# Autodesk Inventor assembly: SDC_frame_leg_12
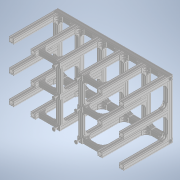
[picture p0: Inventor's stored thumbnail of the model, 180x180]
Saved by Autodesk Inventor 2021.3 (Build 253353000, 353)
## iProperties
Created: 2022-02
Part Number: SDC_frame_leg_12
Description: CAx-IF Rec.Pracs.---Model Styling and Organization---1.2---2011-12-15
Document SubType Name: Assembly
Designer: kengo
Title: SDC_frame_leg_12.stp
Sending System: 3D_Kernel_IO2017 Sp2 by CT CoreTechnologie
Preprocessor: STEP Interface 2017 Sp2 by CT CoreTechnologie
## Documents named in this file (102)
- C:\Users\kengo\Documents\S2S_frame\SDC345\frame_misumi_ver12\SDC_frame_leg_12.iam
- C:\Users\kengo\Documents\S2S_frame\SDC345\frame_misumi_ver12\HBLFSDW8-90-SET(1).iam
- C:\Users\kengo\Documents\S2S_frame\SDC345\frame_misumi_ver12\HBLFSDW8-90-SET(2).iam
- C:\Users\kengo\Documents\S2S_frame\SDC345\frame_misumi_ver12\HBLFSDW8-90-SET(3).iam
- C:\Users\kengo\Documents\S2S_frame\SDC345\frame_misumi_ver12\HBLFSDW8-90-SET(4).iam
- C:\Users\kengo\Documents\S2S_frame\SDC345\frame_misumi_ver12\HBLFSDW8-90-SET(5).iam
- C:\Users\kengo\Documents\S2S_frame\SDC345\frame_misumi_ver12\HBLFSDW8-90-SET(6).iam
- C:\Users\kengo\Documents\S2S_frame\SDC345\frame_misumi_ver12\HBLFSDW8-90-SET(7).iam
- C:\Users\kengo\Documents\S2S_frame\SDC345\frame_misumi_ver12\HBLFSDW8-90-SET(8).iam
- C:\Users\kengo\Documents\S2S_frame\SDC345\frame_misumi_ver12\HBLFSDW8-90-SET(9).iam
- C:\Users\kengo\Documents\S2S_frame\SDC345\frame_misumi_ver12\HBLFSDW8-90-SET(10).iam
- C:\Users\kengo\Documents\S2S_frame\SDC345\frame_misumi_ver12\HBLFSDW8-90-SET(11).iam
- C:\Users\kengo\Documents\S2S_frame\SDC345\frame_misumi_ver12\HBLFSDW8-90-SET(12).iam
- C:\Users\kengo\Documents\S2S_frame\SDC345\frame_misumi_ver12\HBLFSDW8-90-SET(13).iam
- C:\Users\kengo\Documents\S2S_frame\SDC345\frame_misumi_ver12\HBLFSDW8-90-SET(14).iam
- C:\Users\kengo\Documents\S2S_frame\SDC345\frame_misumi_ver12\HBLFSDW8-90-SET(15).iam
- C:\Users\kengo\Documents\S2S_frame\SDC345\frame_misumi_ver12\HBLFSDW8-90-SET(16).iam
- C:\Users\kengo\Documents\S2S_frame\SDC345\frame_misumi_ver12\HBLFSDW8-90-SET(17).iam
- C:\Users\kengo\Documents\S2S_frame\SDC345\frame_misumi_ver12\HBLFSDW8-90-SET(18).iam
- C:\Users\kengo\Documents\S2S_frame\SDC345\frame_misumi_ver12\HBLFSDW8-90-SET(19).iam
- C:\Users\kengo\Documents\S2S_frame\SDC345\frame_misumi_ver12\HBLFSDW8-90-SET(20).iam
- C:\Users\kengo\Documents\S2S_frame\SDC345\frame_misumi_ver12\HBLFSDW8-90-SET(21).iam
- C:\Users\kengo\Documents\S2S_frame\SDC345\frame_misumi_ver12\HBLFSDW8-90-SET(22).iam
- C:\Users\kengo\Documents\S2S_frame\SDC345\frame_misumi_ver12\HBLFSDW8-90-SET(23).iam
- C:\Users\kengo\Documents\S2S_frame\SDC345\frame_misumi_ver12\HBLFSDW8-90-SET(24).iam
- C:\Users\kengo\Documents\S2S_frame\SDC345\frame_misumi_ver12\HBLFSDW8-90-SET(25).iam
- C:\Users\kengo\Documents\S2S_frame\SDC345\frame_misumi_ver12\HBLFSDW8-90-SET(26).iam
- C:\Users\kengo\Documents\S2S_frame\SDC345\frame_misumi_ver12\HBLFSDW8-90-SET(27).iam
- C:\Users\kengo\Documents\S2S_frame\SDC345\frame_misumi_ver12\HBLFSDW8-90-SET(28).iam
- C:\Users\kengo\Documents\S2S_frame\SDC345\frame_misumi_ver12\HBLFSDW8-90-SET(29).iam
- C:\Users\kengo\Documents\S2S_frame\SDC345\frame_misumi_ver12\HBLFSDW8-90-SET(30).iam
- C:\Users\kengo\Documents\S2S_frame\SDC345\frame_misumi_ver12\HBLFSDW8-90-SET(31).iam
- C:\Users\kengo\Documents\S2S_frame\SDC345\frame_misumi_ver12\HBLFSDW8-90-SET(32).iam
- C:\Users\kengo\Documents\S2S_frame\SDC345\frame_misumi_ver12\GNFS8-9090-810.ipt
- C:\Users\kengo\Documents\S2S_frame\SDC345\frame_misumi_ver12\GNFS8-9090-755-LTP.ipt
- C:\Users\kengo\Documents\S2S_frame\SDC345\frame_misumi_ver12\GNFS8-9090-2120.ipt
- C:\Users\kengo\Documents\S2S_frame\SDC345\frame_misumi_ver12\GNFS8-9090-910.ipt
- C:\Users\kengo\Documents\S2S_frame\SDC345\frame_misumi_ver12\HBLFSDW8-90-SET(33).iam
- C:\Users\kengo\Documents\S2S_frame\SDC345\frame_misumi_ver12\HBLFSDW8-90-SET(34).iam
- C:\Users\kengo\Documents\S2S_frame\SDC345\frame_misumi_ver12\HBLFSDW8-90-SET(35).iam
- C:\Users\kengo\Documents\S2S_frame\SDC345\frame_misumi_ver12\HBLFSDW8-90-SET(36).iam
- C:\Users\kengo\Documents\S2S_frame\SDC345\frame_misumi_ver12\HBLFSDW8-90-SET(37).iam
- C:\Users\kengo\Documents\S2S_frame\SDC345\frame_misumi_ver12\HBLFSDW8-90-SET(38).iam
- C:\Users\kengo\Documents\S2S_frame\SDC345\frame_misumi_ver12\HBLFSDW8-90-SET(39).iam
- C:\Users\kengo\Documents\S2S_frame\SDC345\frame_misumi_ver12\HBLFSDW8-90-SET(40).iam
- C:\Users\kengo\Documents\S2S_frame\SDC345\frame_misumi_ver12\HBLFSDW8-90-SET(41).iam
- C:\Users\kengo\Documents\S2S_frame\SDC345\frame_misumi_ver12\HBLFSDW8-90-SET(42).iam
- C:\Users\kengo\Documents\S2S_frame\SDC345\frame_misumi_ver12\HBLFSDW8-90-SET(43).iam
- C:\Users\kengo\Documents\S2S_frame\SDC345\frame_misumi_ver12\HBLFSDW8-90-SET(44).iam
- C:\Users\kengo\Documents\S2S_frame\SDC345\frame_misumi_ver12\HBLFSDW8-90-SET(45).iam
- C:\Users\kengo\Documents\S2S_frame\SDC345\frame_misumi_ver12\GNFS8-4590-410.ipt
- C:\Users\kengo\Documents\S2S_frame\SDC345\frame_misumi_ver12\HBLFSDW8-90-SET(46).iam
- C:\Users\kengo\Documents\S2S_frame\SDC345\frame_misumi_ver12\HBLFSDW8-90-SET(47).iam
- C:\Users\kengo\Documents\S2S_frame\SDC345\frame_misumi_ver12\HBLFSDW8-90-SET(48).iam
- C:\Users\kengo\Documents\S2S_frame\SDC345\frame_misumi_ver12\HBLFSDW8-90-SET(49).iam
- C:\Users\kengo\Documents\S2S_frame\SDC345\frame_misumi_ver12\HBLFSDW8-90-SET(50).iam
- C:\Users\kengo\Documents\S2S_frame\SDC345\frame_misumi_ver12\HBLFSDW8-90-SET(51).iam
- C:\Users\kengo\Documents\S2S_frame\SDC345\frame_misumi_ver12\HBLFSDW8-90-SET(52).iam
- C:\Users\kengo\Documents\S2S_frame\SDC345\frame_misumi_ver12\HBLFSDW8-90-SET(53).iam
- C:\Users\kengo\Documents\S2S_frame\SDC345\frame_misumi_ver12\GLF8-9090-20.ipt
- C:\Users\kengo\Documents\S2S_frame\SDC345\frame_misumi_ver12\HBLFSDW8-90-SET(54).iam
- C:\Users\kengo\Documents\S2S_frame\SDC345\frame_misumi_ver12\HBLFSDW8-90-SET(55).iam
- C:\Users\kengo\Documents\S2S_frame\SDC345\frame_misumi_ver12\GNFS8-4590-320.ipt
- C:\Users\kengo\Documents\S2S_frame\SDC345\frame_misumi_ver12\HBLFSDW8-90-SET(56).iam
- C:\Users\kengo\Documents\S2S_frame\SDC345\frame_misumi_ver12\HBLFSDW8-90-SET(57).iam
- C:\Users\kengo\Documents\S2S_frame\SDC345\frame_misumi_ver12\HBLFSN8-45-SET(1).iam
- C:\Users\kengo\Documents\S2S_frame\SDC345\frame_misumi_ver12\HBLFSDW8-90-SET(58).iam
- C:\Users\kengo\Documents\S2S_frame\SDC345\frame_misumi_ver12\HBLFSDW8-90-SET(59).iam
- C:\Users\kengo\Documents\S2S_frame\SDC345\frame_misumi_ver12\HBLFSN8-45-SET(2).iam
- C:\Users\kengo\Documents\S2S_frame\SDC345\frame_misumi_ver12\HBLFSN8-45-SET(3).iam
- C:\Users\kengo\Documents\S2S_frame\SDC345\frame_misumi_ver12\HBLFSDW8-90-SET(60).iam
- C:\Users\kengo\Documents\S2S_frame\SDC345\frame_misumi_ver12\HBLFSDW8-90-SET(61).iam
- C:\Users\kengo\Documents\S2S_frame\SDC345\frame_misumi_ver12\HBLFSN8-45-SET(4).iam
- C:\Users\kengo\Documents\S2S_frame\SDC345\frame_misumi_ver12\HBLFSDW8-90-SET(62).iam
- C:\Users\kengo\Documents\S2S_frame\SDC345\frame_misumi_ver12\HBLFSDW8-90-SET(63).iam
- C:\Users\kengo\Documents\S2S_frame\SDC345\frame_misumi_ver12\HBLFSN8-45-SET(5).iam
- C:\Users\kengo\Documents\S2S_frame\SDC345\frame_misumi_ver12\HBLFSDW8-90-SET(64).iam
- C:\Users\kengo\Documents\S2S_frame\SDC345\frame_misumi_ver12\HBLFSDW8-90-SET(65).iam
- C:\Users\kengo\Documents\S2S_frame\SDC345\frame_misumi_ver12\HBLFSN8-45-SET(6).iam
- C:\Users\kengo\Documents\S2S_frame\SDC345\frame_misumi_ver12\HBLFSN8-45-SET(7).iam
- C:\Users\kengo\Documents\S2S_frame\SDC345\frame_misumi_ver12\HBLFSDW8-90-SET(66).iam
- C:\Users\kengo\Documents\S2S_frame\SDC345\frame_misumi_ver12\HBLFSDW8-90-SET(67).iam
- C:\Users\kengo\Documents\S2S_frame\SDC345\frame_misumi_ver12\HBLFSN8-45-SET(8).iam
- C:\Users\kengo\Documents\S2S_frame\SDC345\frame_misumi_ver12\HBLFSDW8-90-SET(68).iam
- C:\Users\kengo\Documents\S2S_frame\SDC345\frame_misumi_ver12\HBLFSDW8-90-SET(69).iam
- C:\Users\kengo\Documents\S2S_frame\SDC345\frame_misumi_ver12\HBLFSDW8-90-SET(70).iam
- C:\Users\kengo\Documents\S2S_frame\SDC345\frame_misumi_ver12\HBLFSDW8-90-SET(71).iam
- C:\Users\kengo\Documents\S2S_frame\SDC345\frame_misumi_ver12\HBLFSDW8-90-SET(72).iam
- C:\Users\kengo\Documents\S2S_frame\SDC345\frame_misumi_ver12\HBLFSDW8-90-SET(73).iam
- C:\Users\kengo\Documents\S2S_frame\SDC345\frame_misumi_ver12\HBLFSDW8-90-SET(74).iam
- C:\Users\kengo\Documents\S2S_frame\SDC345\frame_misumi_ver12\HBLFSDW8-90-SET(75).iam
- C:\Users\kengo\Documents\S2S_frame\SDC345\frame_misumi_ver12\HBLFSDW8-90-SET(76).iam
- C:\Users\kengo\Documents\S2S_frame\SDC345\frame_misumi_ver12\HBLFSDW8-90-SET(77).iam
- C:\Users\kengo\Documents\S2S_frame\SDC345\frame_misumi_ver12\HBLFSDW8-90-SET(78).iam
- C:\Users\kengo\Documents\S2S_frame\SDC345\frame_misumi_ver12\HBLFSDW8-90-SET(79).iam
- C:\Users\kengo\Documents\S2S_frame\SDC345\frame_misumi_ver12\HBLFSDW8-90-SET(80).iam
- C:\Users\kengo\Documents\S2S_frame\SDC345\frame_misumi_ver12\HBLFSDW8-90-SET(81).iam
- C:\Users\kengo\Documents\S2S_frame\SDC345\frame_misumi_ver12\HBLFSDW8-90-SET(82).iam
- C:\Users\kengo\Documents\S2S_frame\SDC345\frame_misumi_ver12\HBLFSDW8-90-SET(83).iam
- C:\Users\kengo\Documents\S2S_frame\SDC345\frame_misumi_ver12\HBLFSDW8-90-SET(84).iam
- C:\Users\kengo\Documents\S2S_frame\SDC345\frame_misumi_ver12\FJFNS20-150.iam
- C:\Users\kengo\Documents\S2S_frame\SDC345\frame_misumi_ver12\CBM12-25.ipt
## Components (164 placed, 101 different names)
1. HBLFSDW8-90-SET(1) [sub-assembly]
2. HBLFSDW8-90-SET(2) [sub-assembly]
3. HBLFSDW8-90-SET(3) [sub-assembly]
4. HBLFSDW8-90-SET(4) [sub-assembly]
5. HBLFSDW8-90-SET(5) [sub-assembly]
6. HBLFSDW8-90-SET(6) [sub-assembly]
7. HBLFSDW8-90-SET(7) [sub-assembly]
8. HBLFSDW8-90-SET(8) [sub-assembly]
9. HBLFSDW8-90-SET(9) [sub-assembly]
10. HBLFSDW8-90-SET(10) [sub-assembly]
11. HBLFSDW8-90-SET(11) [sub-assembly]
12. HBLFSDW8-90-SET(12) [sub-assembly]
13. HBLFSDW8-90-SET(13) [sub-assembly]
14. HBLFSDW8-90-SET(14) [sub-assembly]
15. HBLFSDW8-90-SET(15) [sub-assembly]
16. HBLFSDW8-90-SET(16) [sub-assembly]
17. HBLFSDW8-90-SET(17) [sub-assembly]
18. HBLFSDW8-90-SET(18) [sub-assembly]
19. HBLFSDW8-90-SET(19) [sub-assembly]
20. HBLFSDW8-90-SET(20) [sub-assembly]
21. HBLFSDW8-90-SET(21) [sub-assembly]
22. HBLFSDW8-90-SET(22) [sub-assembly]
23. HBLFSDW8-90-SET(23) [sub-assembly]
24. HBLFSDW8-90-SET(24) [sub-assembly]
25. HBLFSDW8-90-SET(25) [sub-assembly]
26. HBLFSDW8-90-SET(26) [sub-assembly]
27. HBLFSDW8-90-SET(27) [sub-assembly]
28. HBLFSDW8-90-SET(28) [sub-assembly]
29. HBLFSDW8-90-SET(29) [sub-assembly]
30. HBLFSDW8-90-SET(30) [sub-assembly]
31. HBLFSDW8-90-SET(31) [sub-assembly]
32. HBLFSDW8-90-SET(32) [sub-assembly]
33. GNFS8-9090-810
34. GNFS8-9090-810:1
35. GNFS8-9090-810:2
36. GNFS8-9090-755-LTP
37. GNFS8-9090-755-LTP:1
38. GNFS8-9090-2120
39. GNFS8-9090-810:3
40. GNFS8-9090-810:4
41. GNFS8-9090-810:5
42. GNFS8-9090-755-LTP:2
43. GNFS8-9090-755-LTP:3
44. GNFS8-9090-2120:1
45. GNFS8-9090-810:6
46. GNFS8-9090-810:7
47. GNFS8-9090-910
48. GNFS8-9090-910:1
49. GNFS8-9090-910:2
50. GNFS8-9090-910:3
51. GNFS8-9090-910:4
52. GNFS8-9090-910:5
53. GNFS8-9090-810:8
54. GNFS8-9090-810:9
55. GNFS8-9090-810:10
56. GNFS8-9090-755-LTP:4
57. GNFS8-9090-755-LTP:5
58. GNFS8-9090-810:11
59. HBLFSDW8-90-SET(33) [sub-assembly]
60. HBLFSDW8-90-SET(34) [sub-assembly]
61. HBLFSDW8-90-SET(35) [sub-assembly]
62. HBLFSDW8-90-SET(36) [sub-assembly]
63. HBLFSDW8-90-SET(37) [sub-assembly]
64. HBLFSDW8-90-SET(38) [sub-assembly]
65. HBLFSDW8-90-SET(39) [sub-assembly]
66. HBLFSDW8-90-SET(40) [sub-assembly]
67. HBLFSDW8-90-SET(41) [sub-assembly]
68. HBLFSDW8-90-SET(42) [sub-assembly]
69. HBLFSDW8-90-SET(43) [sub-assembly]
70. HBLFSDW8-90-SET(44) [sub-assembly]
71. HBLFSDW8-90-SET(45) [sub-assembly]
72. GNFS8-4590-410
73. HBLFSDW8-90-SET(46) [sub-assembly]
74. HBLFSDW8-90-SET(47) [sub-assembly]
75. GNFS8-4590-410:1
76. HBLFSDW8-90-SET(48) [sub-assembly]
77. HBLFSDW8-90-SET(49) [sub-assembly]
78. GNFS8-4590-410:2
79. HBLFSDW8-90-SET(50) [sub-assembly]
80. HBLFSDW8-90-SET(51) [sub-assembly]
81. GNFS8-4590-410:3
82. HBLFSDW8-90-SET(52) [sub-assembly]
83. HBLFSDW8-90-SET(53) [sub-assembly]
84. GLF8-9090-20
85. GLF8-9090-20:1
86. GLF8-9090-20:2
87. GLF8-9090-20:3
88. GLF8-9090-20:4
89. GLF8-9090-20:5
90. HBLFSDW8-90-SET(54) [sub-assembly]
91. HBLFSDW8-90-SET(55) [sub-assembly]
92. GNFS8-4590-320
93. HBLFSDW8-90-SET(56) [sub-assembly]
94. HBLFSDW8-90-SET(57) [sub-assembly]
95. HBLFSN8-45-SET(1) [sub-assembly]
96. GNFS8-4590-320:1
97. HBLFSDW8-90-SET(58) [sub-assembly]
98. HBLFSDW8-90-SET(59) [sub-assembly]
99. HBLFSN8-45-SET(2) [sub-assembly]
100. HBLFSN8-45-SET(3) [sub-assembly]
101. GNFS8-4590-320:2
102. HBLFSDW8-90-SET(60) [sub-assembly]
103. HBLFSDW8-90-SET(61) [sub-assembly]
104. HBLFSN8-45-SET(4) [sub-assembly]
105. GNFS8-4590-320:3
106. HBLFSDW8-90-SET(62) [sub-assembly]
107. HBLFSDW8-90-SET(63) [sub-assembly]
108. HBLFSN8-45-SET(5) [sub-assembly]
109. GNFS8-4590-320:4
110. HBLFSDW8-90-SET(64) [sub-assembly]
111. HBLFSDW8-90-SET(65) [sub-assembly]
112. HBLFSN8-45-SET(6) [sub-assembly]
113. HBLFSN8-45-SET(7) [sub-assembly]
114. GNFS8-4590-320:5
115. HBLFSDW8-90-SET(66) [sub-assembly]
116. HBLFSDW8-90-SET(67) [sub-assembly]
117. HBLFSN8-45-SET(8) [sub-assembly]
118. HBLFSDW8-90-SET(68) [sub-assembly]
119. HBLFSDW8-90-SET(69) [sub-assembly]
120. HBLFSDW8-90-SET(70) [sub-assembly]
121. HBLFSDW8-90-SET(71) [sub-assembly]
122. HBLFSDW8-90-SET(72) [sub-assembly]
123. HBLFSDW8-90-SET(73) [sub-assembly]
124. HBLFSDW8-90-SET(74) [sub-assembly]
125. HBLFSDW8-90-SET(75) [sub-assembly]
126. HBLFSDW8-90-SET(76) [sub-assembly]
127. HBLFSDW8-90-SET(77) [sub-assembly]
128. HBLFSDW8-90-SET(78) [sub-assembly]
129. HBLFSDW8-90-SET(79) [sub-assembly]
130. HBLFSDW8-90-SET(80) [sub-assembly]
131. HBLFSDW8-90-SET(81) [sub-assembly]
132. HBLFSDW8-90-SET(82) [sub-assembly]
133. HBLFSDW8-90-SET(83) [sub-assembly]
134. HBLFSDW8-90-SET(84) [sub-assembly]
135. FJFNS20-150 [sub-assembly]
136. CBM12-25
137. CBM12-25:1
138. CBM12-25:2
139. CBM12-25:3
140. FJFNS20-150:1 [sub-assembly]
141. CBM12-25:4
142. CBM12-25:5
143. CBM12-25:6
144. CBM12-25:7
145. FJFNS20-150:2 [sub-assembly]
146. CBM12-25:8
147. CBM12-25:9
148. CBM12-25:10
149. CBM12-25:11
150. FJFNS20-150:3 [sub-assembly]
151. CBM12-25:12
152. CBM12-25:13
153. CBM12-25:14
154. CBM12-25:15
155. FJFNS20-150:4 [sub-assembly]
156. CBM12-25:16
157. CBM12-25:17
158. CBM12-25:18
159. CBM12-25:19
160. FJFNS20-150:5 [sub-assembly]
161. CBM12-25:20
162. CBM12-25:21
163. CBM12-25:22
164. CBM12-25:23
